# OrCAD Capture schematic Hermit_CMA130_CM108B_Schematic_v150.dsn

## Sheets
1 01. Release Note: title: CM108B Reference Circuit; rev: 1.5.0; company: C-MEDIA ELECTRONICS Inc.; note: Release Note; note: 6F., 100, Sec. 4, Civil Boulevard, Taipei, Taiwan, R.O.C.
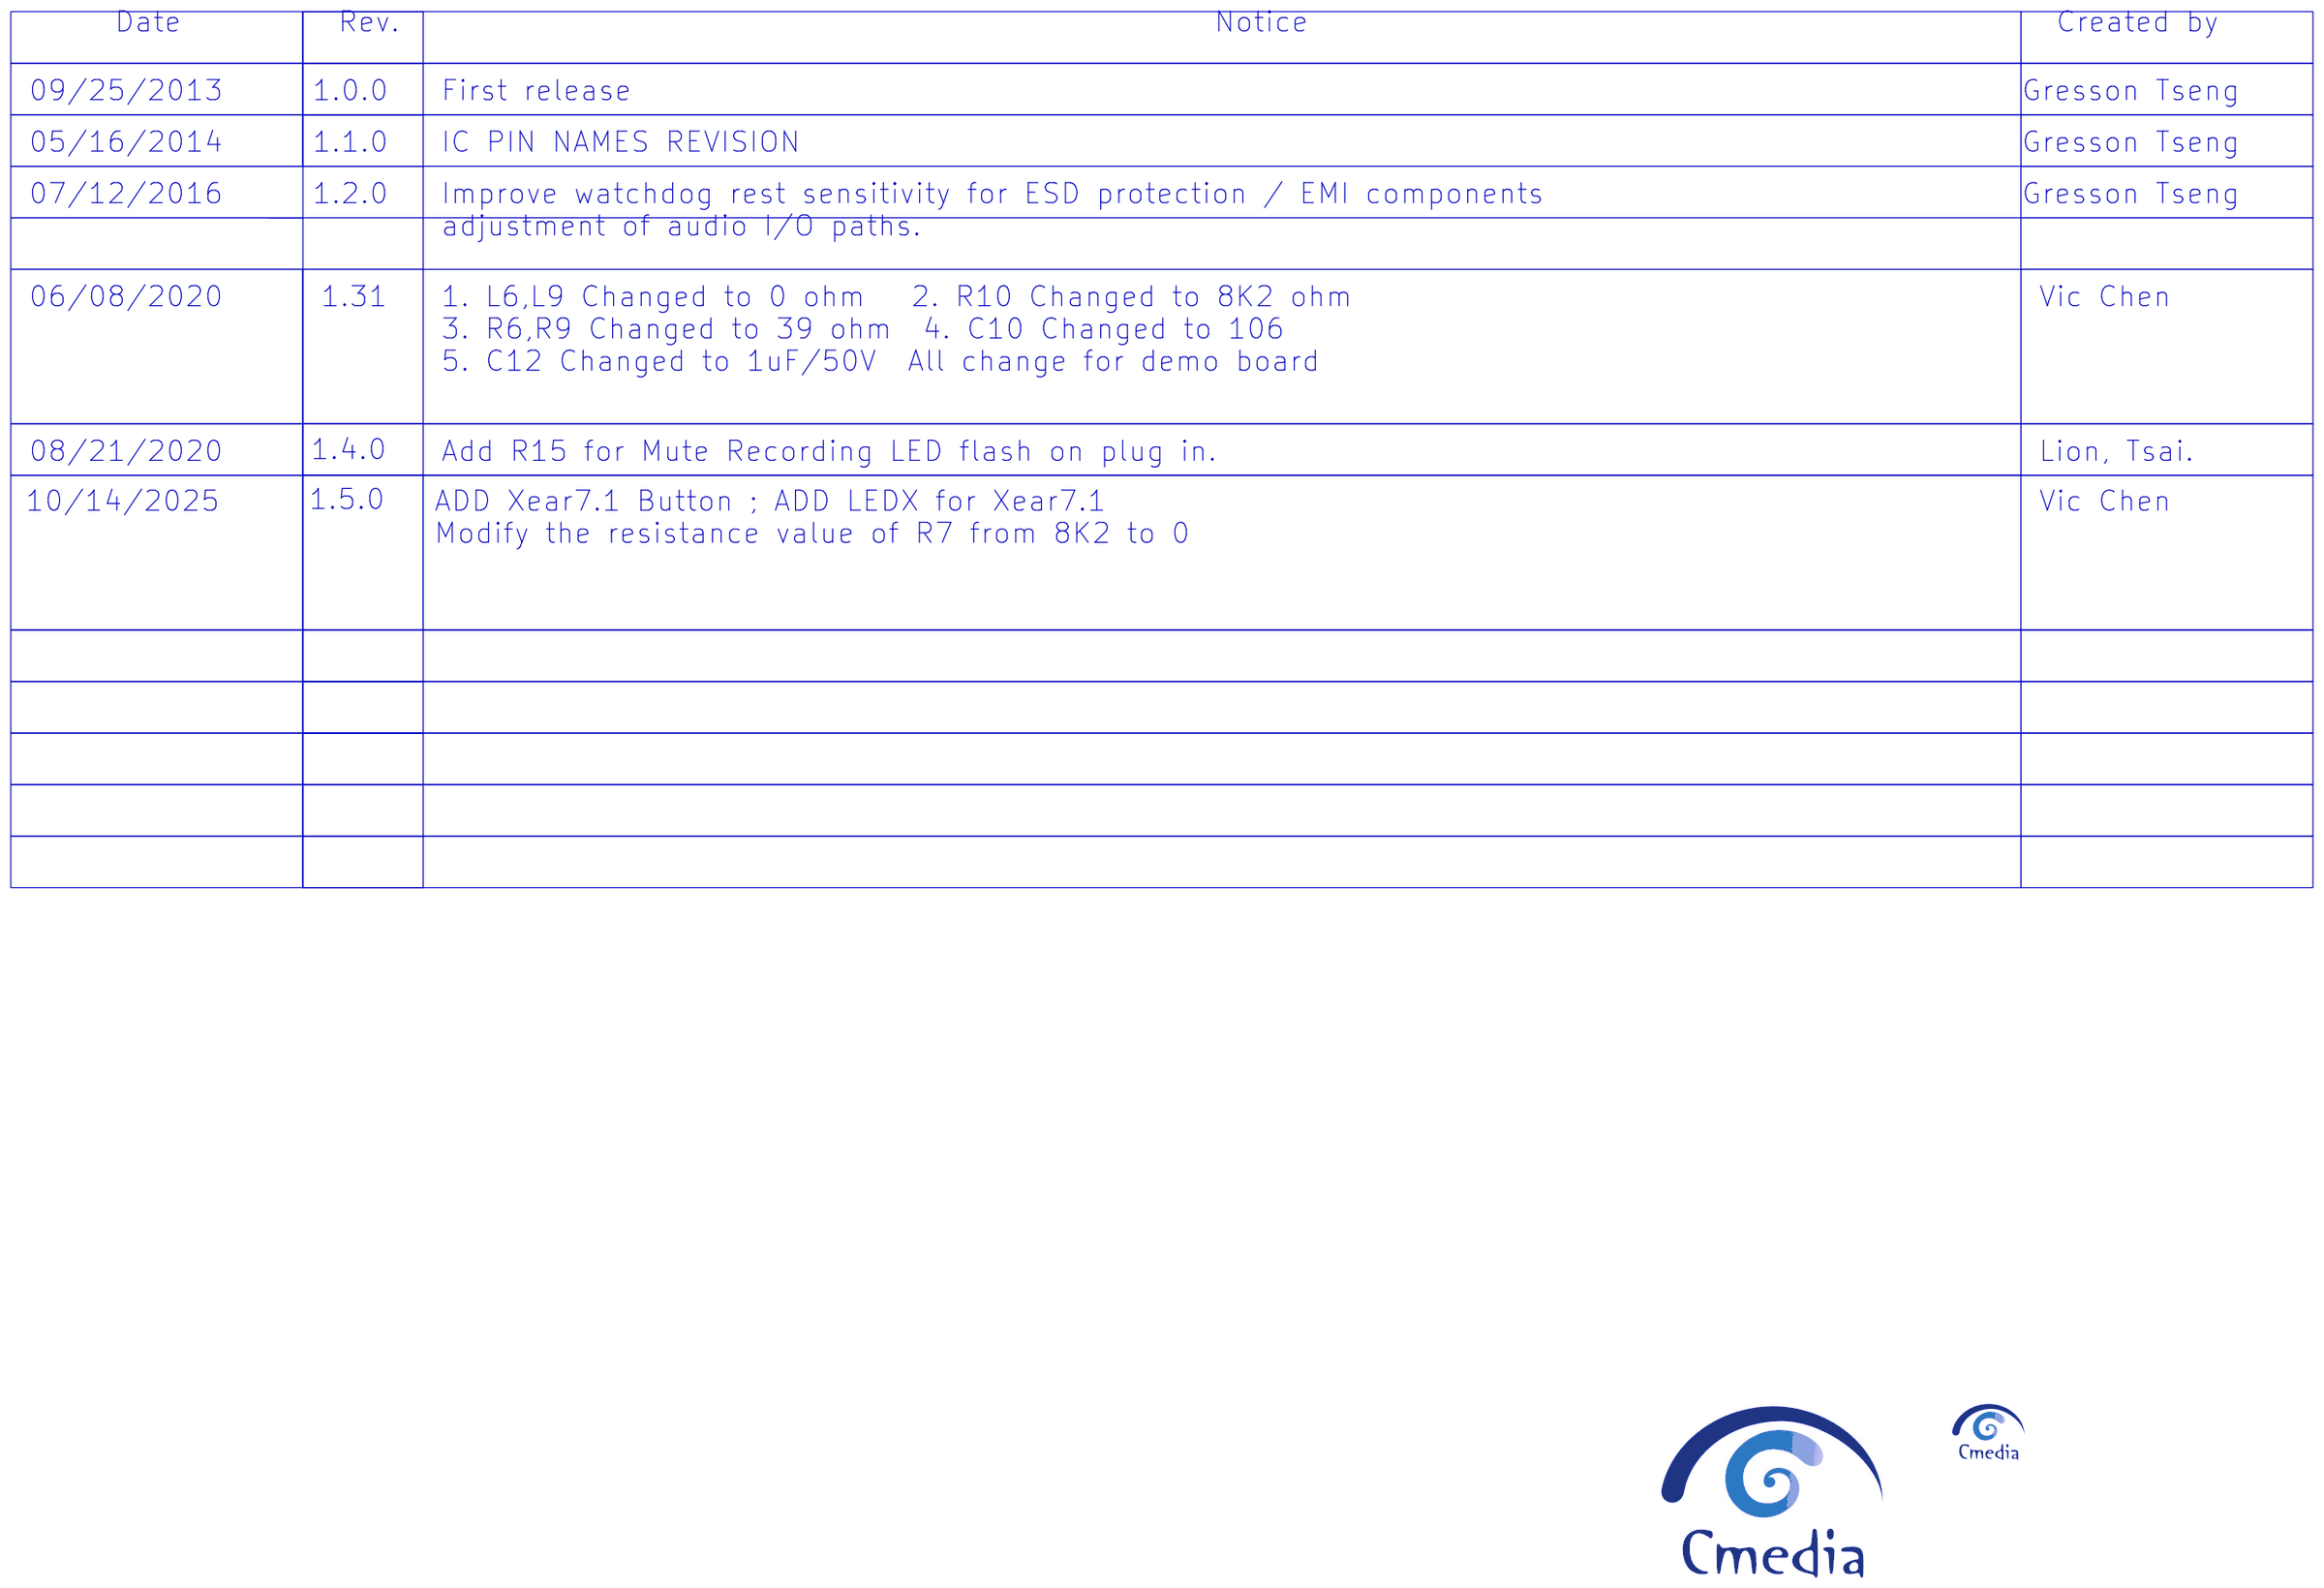
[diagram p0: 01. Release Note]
2 02. Block Diagram: note: Block Diagram
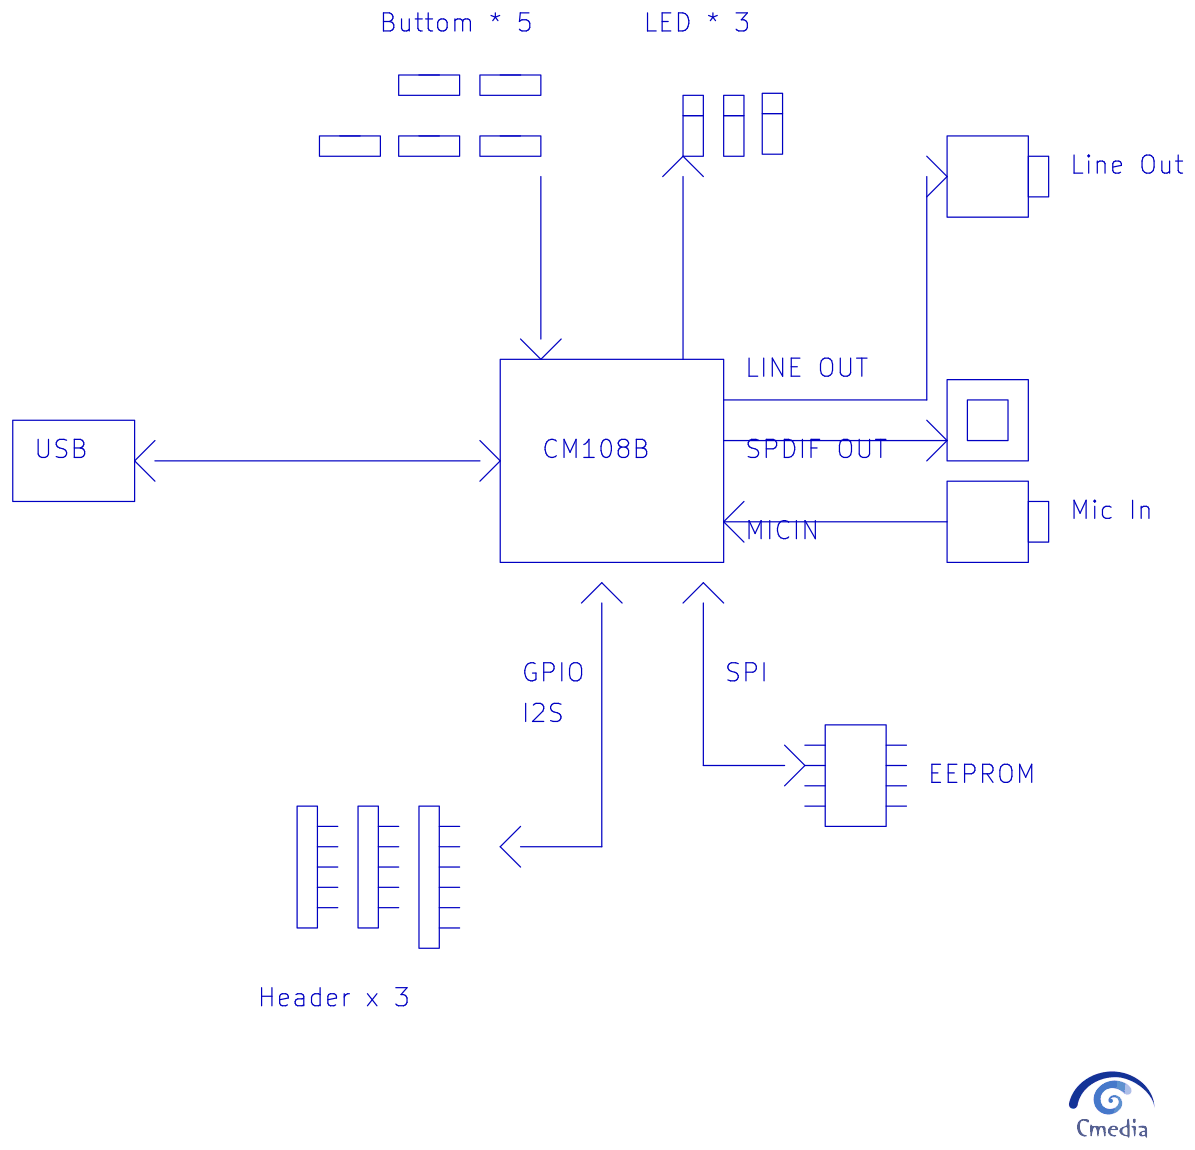
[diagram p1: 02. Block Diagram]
3 03. Schematic: size A4; note: Schematic
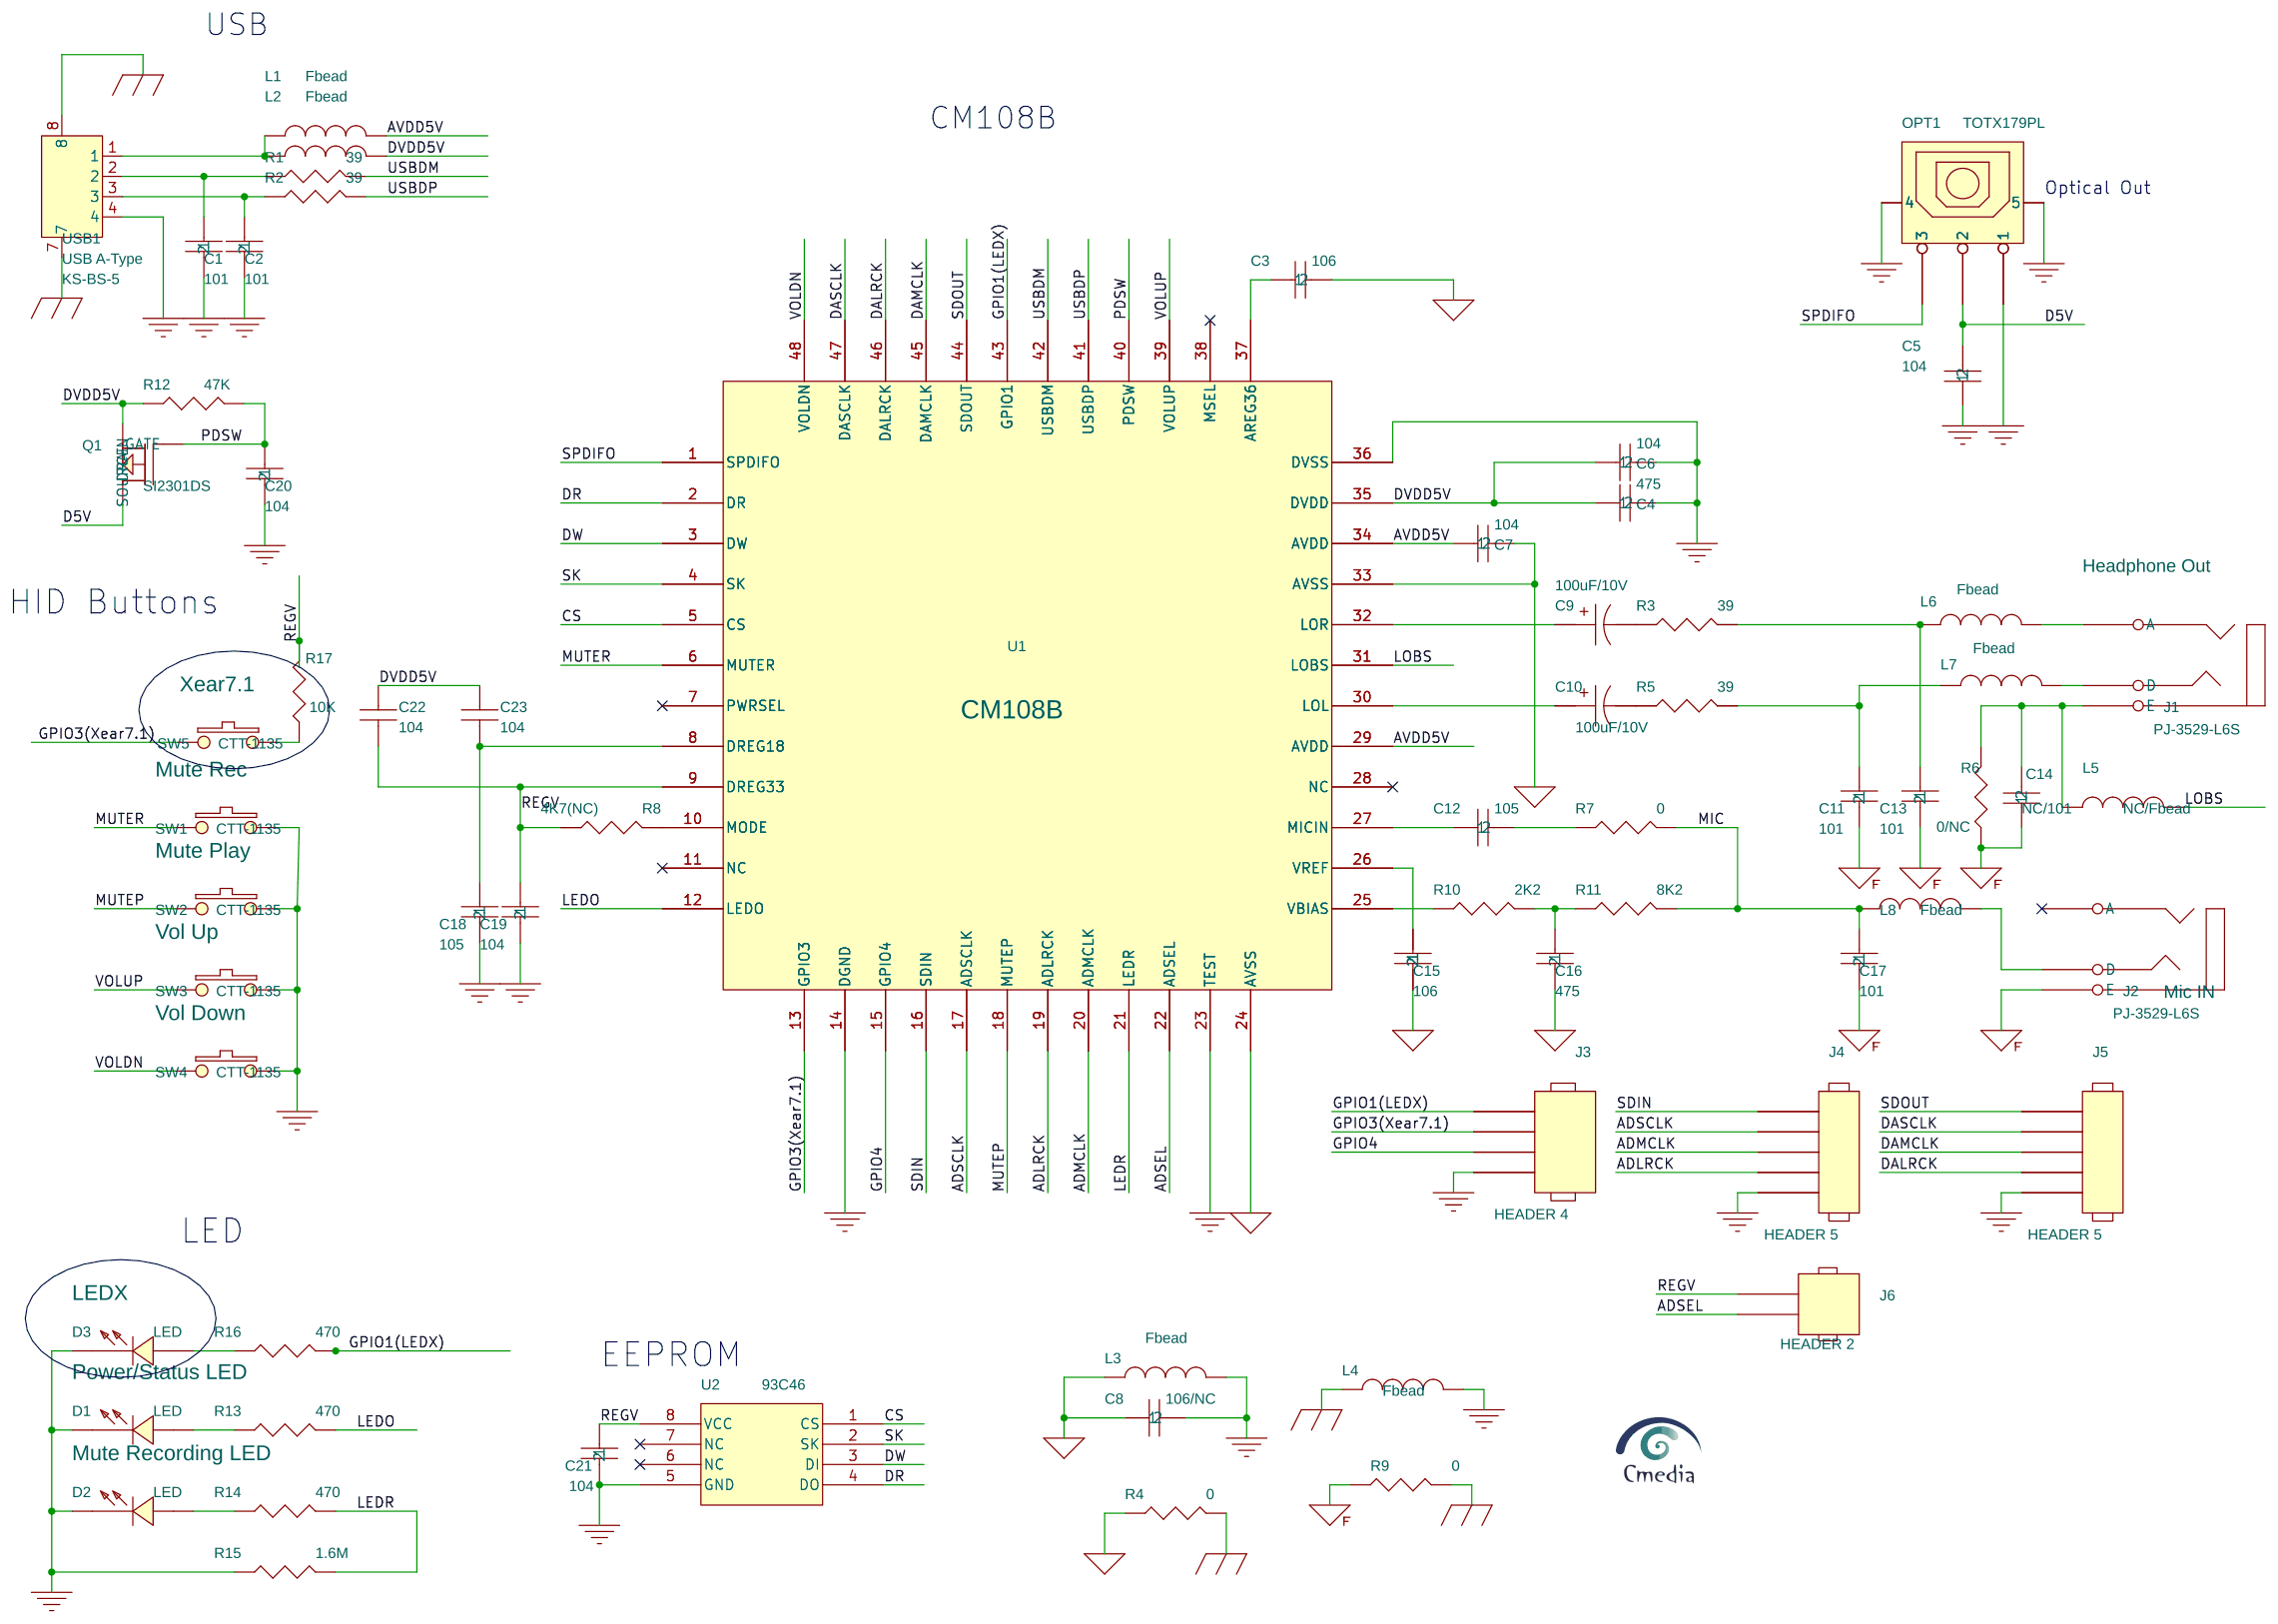
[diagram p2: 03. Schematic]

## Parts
C1  101  [C0603]
C2  101  [C0603]
C3  106  [C0603]
C4  475  [C0603]
C5  104  [SM/C_0603]
C6  104  [C0603]
C7  104  [C0603]
C8  106/NC  [C0603]
C9  100uF/10V  [5x7]
C10  100uF/10V  [5x7]
C11  101  [C0603]
C12  105  [C0603]
C13  101  [C0603]
C14  NC/101  [C0603]
C15  106  [C0603]
C16  475  [C0603]
C17  101  [C0603]
C18  105  [C0603]
C19  104  [C0603]
C20  104  [C0603]
C21  104  [C0603]
C22  104
C23  104
D1  LED  [D0603]
D2  LED  [D0603]
D3  LED  [D0603]
J1  PJ-3529-L6S
J2  PJ-3529-L6S
J3  HEADER 4
J4  HEADER 5
J5  HEADER 5
J6  HEADER 2
L1  Fbead  [L0603]
L2  Fbead  [L0603]
L3  Fbead  [L0603]
L4  Fbead  [L0603]
L5  NC/Fbead  [L0603]
L6  Fbead  [L0603]
L7  Fbead  [L0603]
L8  Fbead  [L0603]
OPT1  TOTX179PL
Q1  SI2301DS  [SOT23-SGD]
R1  39  [R0603]
R2  39  [R0603]
R3  39  [R0603]
R4  0  [R0603]
R5  39  [R0603]
R6  0/NC  [R0603]
R7  0  [R0603]
R8  4K7(NC)  [R0603]
R9  0  [R0603]
R10  2K2  [R0603]
R11  8K2  [R0603]
R12  47K  [R0603]
R13  470  [R0603]
R14  470  [R0603]
R15  1.6M
R16  470  [R0603]
R17  10K  [R0603]
SW1  CTT-1135
SW2  CTT-1135
SW3  CTT-1135
SW4  CTT-1135
SW5  CTT-1135
U1  CM108B  [LQFP-48]
U2  93C46  [SOP-8]
USB1  KS-BS-5  [USB-TYPEB-SMD]

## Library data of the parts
C1 = CAP_NP_1
C2 = CAP_NP_11
C3 = CAP_NP_13
C4 = CAP_NP_12
C5 = CAP_NP_4
C6 = CAP_NP_9
C7 = CAP_NP_8
C8 = CAP_NP_10
C9 = CAP_POL_1
C10 = CAP_POL
C11 = CAP_NP_6
C12 = CAP_NP_18
C13 = CAP_NP_2
C14 = CAP_NP
C15 = CAP_NP_3
C16 = CAP_NP_15
C17 = CAP_NP_17
C18 = CAP_NP_5
C19 = CAP_NP_14
C20 = CAP_NP_16
C21 = CAP_NP_7
C22 C23 = CAPACITOR_NON-POL
D1 = LED: 1ST PART FIELD: Power/Status LED
D2 = LED: 1ST PART FIELD: Mute Recording LED
D3 = LED: 1ST PART FIELD: LEDX
J1 = PHONEJACK_STEREO_SW_0: 1ST PART FIELD: Headphone Out
J2 = PHONEJACK_STEREO_SW_0: 1ST PART FIELD: Mic IN
J3 = HEADER_4
J4 J5 = HEADER_5
J6 = HEADER_2
L1-L8 = INDUCTOR
OPT1 = HEADER_3_2: 1ST PART FIELD: TOTX178
Q1 = MOSFET_P_0_v2
R1-R17 = R
SW1 = SW_TACT-SPST_SM: 1ST PART FIELD: Mute Rec
SW2 = SW_TACT-SPST_SM: 1ST PART FIELD: Mute Play
SW3 = SW_TACT-SPST_SM: 1ST PART FIELD: Vol Up
SW4 = SW_TACT-SPST_SM: 1ST PART FIELD: Vol Down
SW5 = SW_TACT-SPST_SM: 1ST PART FIELD: Xear7.1
U1 = CM072_3
U2 = 93C46: 1ST PART FIELD: Option(93C46)
USB1 = HEADER_4_0: 1ST PART FIELD: USB A-Type

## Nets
AGND: C3.2 C7.2 C8.1 C15.2 C16.2 L3.2 R4.1 U1.24(AVSS) U1.33(AVSS)
AVDD5V: C7.1 L1.1 U1.29(AVDD) U1.34(AVDD)
D5V: C5.2 OPT1.2 Q1.D(DRAIN)
DGND: C1.2 C2.2 C4.2 C5.1 C6.2 C8.2 C18.2 C19.2 C20.2 C21.2 D1.2(CATHODE) D2.2(CATHODE) D3.2(CATHODE) J3.4 J4.5 J5.5 L3.1 L4.1 OPT1.1 OPT1.4 OPT1.5 R15.1 SW1.2 SW2.2 SW3.2 SW4.2 U1.14(DGND) U1.23(TEST) U1.36(DVSS) U2.5(GND) USB1.4
DVDD5V: C4.1 C6.1 C22.1 C23.1 L2.1 Q1.S(SOURCE) R12.1 U1.35(DVDD)
ADLRCK: J4.4 U1.19(ADLRCK)
ADMCLK: J4.3 U1.20(ADMCLK)
ADSCLK: J4.2 U1.17(ADSCLK)
ADSEL: J6.2 U1.22(ADSEL)
CGND: L4.2 R4.2 R9.2 USB1.7 USB1.8
CS: U1.5(CS) U2.1(CS)
DALRCK: J5.4 U1.46(DALRCK)
DAMCLK: J5.3 U1.45(DAMCLK)
DASCLK: J5.2 U1.47(DASCLK)
DR: U1.2(DR) U2.4(DO)
DW: U1.3(DW) U2.3(DI)
GPIO1(LEDX): J3.1 R16.1 U1.43(GPIO1)
GPIO3(Xear7.1): J3.2 SW5.1 U1.13(GPIO3)
GPIO4: J3.3 U1.15(GPIO4)
IO_GND: C11.2 C13.2 C14.1 C17.2 J2.1(E) R6.1 R9.1
LEDO: R13.1 U1.12(LEDO)
LEDR: R14.1 R15.2 U1.21(LEDR)
LOBS: L5.1 U1.31(LOBS)
MIC: C17.1 L8.2 R7.2 R11.2
MUTEP: SW2.1 U1.18(MUTEP)
MUTER: SW1.1 U1.6(MUTER)
PDSW: C20.1 Q1.G(GATE) R12.2 U1.40(PDSW)
REGV: C19.1 C21.1 C22.2 J6.1 R8.2 R17.2 U1.9(DREG33) U2.8(VCC)
SDIN: J4.1 U1.16(SDIN)
SDOUT: J5.1 U1.44(SDOUT)
SK: U1.4(SK) U2.2(SK)
SPDIFO: OPT1.3 U1.1(SPDIFO)
USBDM: R1.2 U1.42(USBDM)
USBDP: R2.2 U1.41(USBDP)
VOLDN: SW4.1 U1.48(VOLDN)
VOLUP: SW3.1 U1.39(VOLUP)
N17092017: C14.2 J1.1(E) L5.2 R6.2
N17092136: C11.1 L7.2 R5.2
N17092201: D1.1(ANODE) R13.2
N17092215: D2.1(ANODE) R14.2
N17092238: C13.1 L6.2 R3.2
N17092243: C16.1 R10.2 R11.1
N17092396: C2.1 R2.1 USB1.3
N17092398: C1.1 R1.1 USB1.2
N17092494: J2.2(D) L8.1
N17092652: C3.1 U1.37(AREG36)
N17092734: C18.1 C23.2 U1.8(DREG18)
N17092854: R10.1 U1.25(VBIAS)
N17092856: C15.1 U1.26(VREF)
N17092860: C12.1 U1.27(MICIN)
N17093082: L1.2 L2.2 USB1.1
N17093109: C9.1 U1.32(LOR)
N17093121: C12.2 R7.1
N17093136: C10.1 U1.30(LOL)
N17253909: J1.3(A) L6.1
N17254176: J1.2(D) L7.1
N17273515: R17.1 SW5.2
N17273838: D3.1(ANODE) R16.2
N17278942: R8.1 U1.10(MODE)
N17278943: C9.2 R3.1
N17278944: C10.2 R5.1

Not connected (* = marked no-connect by the designer): J2 3(A)*; U1 7(PWRSEL)* 11(NC)* 28(NC)* 38(MSEL)*; U2 6(NC)* 7(NC)*

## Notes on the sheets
sheet 1
- Date
- Rev.
- Notice
- Created by
- 09/25/2013
- 1.0.0
- First release
- Gresson Tseng
- 05/16/2014
- 1.1.0
- IC PIN NAMES REVISION
- Gresson Tseng
- 07/12/2016
- 1.2.0
- Improve watchdog rest sensitivity for ESD protection / EMI components
  adjustment of audio I/O paths.
- Gresson Tseng
- 06/08/2020
- 1.31
- 1. L6,L9 Changed to 0 ohm   2. R10 Changed to 8K2 ohm
  3. R6,R9 Changed to 39 ohm  4. C10 Changed to 106
  5. C12 Changed to 1uF/50V  All change for demo board
- Vic Chen
- 08/21/2020
- 1.4.0
- Add R15 for Mute Recording LED flash on plug in.
- Lion, Tsai.
- 10/14/2025
- 1.5.0
- ADD Xear7.1 Button ; ADD LEDX for Xear7.1
  Modify the resistance value of R7 from 8K2 to 0
- Vic Chen
sheet 2
- Buttom * 5
- LED * 3
- Line Out
- LINE OUT
- USB
- CM108B
- SPDIF OUT
- Mic In
- MICIN
- GPIO
- SPI
- I2S
- EEPROM
- Header x 3
sheet 3
- USB
- CM108B
- Optical Out
- HID Buttons
- LED
- EEPROM
